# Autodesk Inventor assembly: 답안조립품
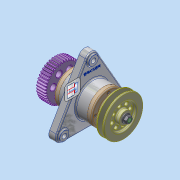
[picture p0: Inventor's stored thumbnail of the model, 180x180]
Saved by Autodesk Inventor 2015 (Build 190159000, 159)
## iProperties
Created: 2023-04
Part Number: 답안조립품
Document SubType Name: Assembly
Designer: SCD-A04
Author: SCD-A04
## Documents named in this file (11)
- C:\Users\SCD-A04\Desktop\730407V1013\답안조립품.iam
- C:\Users\SCD-A04\Desktop\730407V1013\본체.ipt
- C:\Users\SCD-A04\Desktop\730407V1013\축.ipt
- C:\Users\SCD-A04\Desktop\730407V1013\베어링 6204.ipt
- C:\Users\SCD-A04\Desktop\730407V1013\오일 실 20 32 8.ipt
- C:\Users\SCD-A04\Desktop\730407V1013\묻힘키 5x5x16.ipt
- C:\Users\SCD-A04\Desktop\730407V1013\v-벨트풀리.ipt
- C:\Users\SCD-A04\Desktop\730407V1013\6각 플랜지 너트 M10.ipt
- C:\Users\SCD-A04\Desktop\730407V1013\스퍼기어.ipt
- C:\Users\SCD-A04\Desktop\730407V1013\커버.ipt
- C:\Users\SCD-A04\Desktop\730407V1013\볼트 M4 x 12.ipt
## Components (3 placed, 2 different names)
1. v-벨트풀리:1 — 각도:1
2. 6각 플랜지 너트 M10:1
3. 6각 플랜지 너트 M10:2
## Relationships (1: Angle 1)
- 각도:1 [Angle]: v-벨트풀리:1
